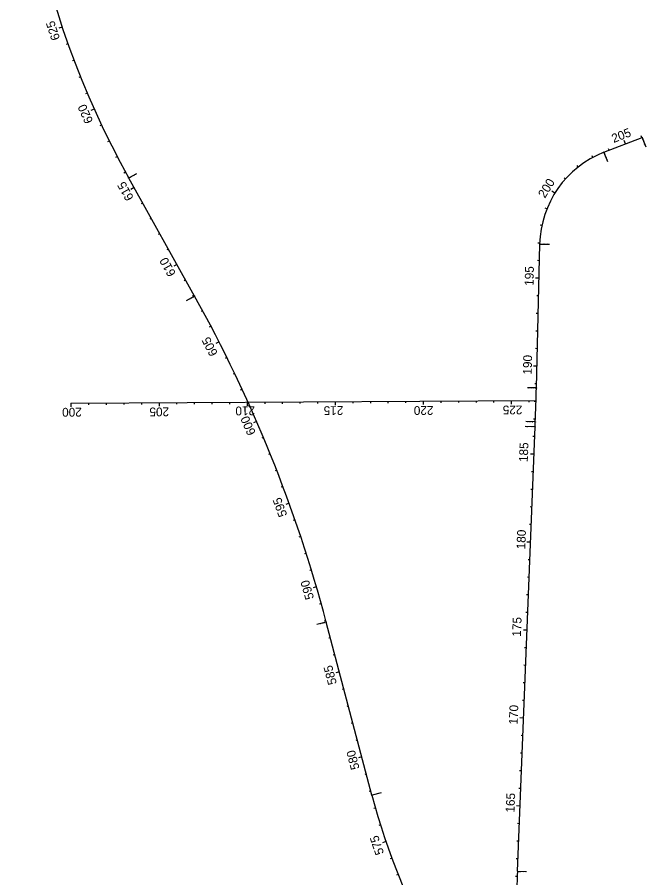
# Model space of a CAD drawing. Extents: x 448091 to 665917, y 1461380 to 1587607.
# Drawn here: x 476716 to 480285, y 1573756 to 1578644 of the extents above; entities that cross this region are included whole.
import ezdxf

# ---------------------------------------------------------------- set-up
doc = ezdxf.new("R2010")
doc.units = 0
for name, color, linetype in [('AttenuatorTM', 7, 'Continuous'), ('BillboardVeg', 7, 'Continuous'), ('BillboardZone', 7, 'Continuous'), ('BLSurvey_dp', 7, 'Continuous'), ('BLSurveyCntrl_ep', 7, 'Continuous'), ('BLSurveyField_ep', 7, 'Continuous'), ('BLSurveySymbl_ep', 7, 'Continuous')]:
    doc.layers.add(name, color=color, linetype=linetype)

msp = doc.modelspace()

# ---------------------------------------------------------------- linework, layer by layer
at = {"layer": 'AttenuatorTM'}
for p, q in [((480264.5, 1577961.2), (480285.3, 1577907.8)), ((480048, 1577875.9), (480068.3, 1577823.8)), ((477350, 1577731), (477394.8, 1577756)), ((479683.5, 1577355.3), (479738.1, 1577354.1)), ((477722.8, 1577059.5), (477676.2, 1577033.5)), ((479663.3, 1576538.6), (479612.9, 1576539.7)), ((479656.1, 1576316.6), (479600.7, 1576318.8)), ((479657.2, 1576345.3), (479604.9, 1576347.4)), ((478470, 1575207.9), (478417.8, 1575194.1)), ((478783.7, 1574238.6), (478731.4, 1574224.8)), ((479557, 1573793.5), (479608.7, 1573791.4))]:
    msp.add_line(p, q, dxfattribs=at)
for centre in [(480264.5, 1577961.2), (480047.7, 1577876.6), (477349.4, 1577730.6), (479682.8, 1577355.3), (477723.4, 1577059.9), (479664, 1576538.5), (479656.8, 1576316.5), (479658, 1576345.3), (478470.7, 1575208.1), (478730.7, 1574224.8), (479556.3, 1573793.5)]:
    msp.add_circle(centre, 0.75, dxfattribs=at)
at = {"layer": 'BillboardVeg'}
for p, q in [((477723.4, 1577059.9), (477349.4, 1577730.6)), ((478730.7, 1574224.8), (478470.7, 1575208.1))]:
    msp.add_line(p, q, dxfattribs=at)
for centre, radius, start, end in [((481716.2, 1580165.9), 5000, 171.5783, 209.1468), ((470736.4, 1573163.5), 8000, 14.80788, 29.14677), ((482597.8, 1575247.1), 4000, 194.8079, 223.3814)]:
    msp.add_arc(centre, radius, start, end, dxfattribs=at)
at = {"layer": 'BLSurvey_dp'}
for p, q in [((476971.9, 1578587.3), (476953, 1578581)), ((477004.5, 1578492.8), (476995, 1578489.4)), ((477038.9, 1578398.9), (477029.5, 1578395.4)), ((477075.1, 1578305.7), (477065.9, 1578302)), ((477113.3, 1578213.3), (477104.1, 1578209.4)), ((477153.2, 1578121.6), (477135, 1578113.4)), ((477195, 1578030.7), (477186, 1578026.5)), ((477238.6, 1577940.8), (477229.7, 1577936.3)), ((477284, 1577851.7), (477275.2, 1577847)), ((477331.2, 1577763.5), (477322.4, 1577758.7)), ((477379.8, 1577676.1), (477362.3, 1577666.3)), ((477428.5, 1577588.7), (477419.8, 1577583.9)), ((477477.2, 1577501.4), (477468.5, 1577496.5)), ((477525.9, 1577414.1), (477517.2, 1577409.2)), ((477574.6, 1577326.7), (477565.9, 1577321.9)), ((477623.3, 1577239.4), (477605.8, 1577229.6)), ((477672, 1577152.1), (477663.3, 1577147.2)), ((477720.7, 1577064.7), (477712, 1577059.8)), ((477768.9, 1576977.1), (477760.1, 1576972.3)), ((477816.1, 1576888.9), (477807.2, 1576884.2)), ((477862.1, 1576800.1), (477844.3, 1576791)), ((477907, 1576710.8), (477898, 1576706.3)), ((477950.7, 1576620.9), (477941.7, 1576616.5)), ((477993.4, 1576530.4), (477984.3, 1576526.2)), ((478034.9, 1576439.4), (478025.8, 1576435.3)), ((478075.3, 1576348), (478057, 1576340)), ((478114.5, 1576256), (478105.3, 1576252.1)), ((478152.6, 1576163.5), (478143.3, 1576159.8)), ((478189.5, 1576070.6), (478180.2, 1576066.9)), ((478225.3, 1575977.2), (478215.9, 1575973.7)), ((478259.9, 1575883.4), (478241.1, 1575876.6)), ((478293.3, 1575789.1), (478283.8, 1575785.8)), ((478325.5, 1575694.4), (478316, 1575691.3)), ((478356.6, 1575599.4), (478347, 1575596.3)), ((478386.4, 1575503.9), (478376.8, 1575501)), ((478415.1, 1575408.1), (478395.9, 1575402.5)), ((478442.5, 1575312), (478432.9, 1575309.3)), ((478468.8, 1575215.5), (478459.1, 1575212.9)), ((478494.3, 1575118.8), (478484.7, 1575116.3)), ((478519.9, 1575022.1), (478510.2, 1575019.6)), ((478545.5, 1574925.5), (478526.1, 1574920.3)), ((478571, 1574828.8), (478561.3, 1574826.2)), ((478596.6, 1574732.1), (478586.9, 1574729.5)), ((478622.1, 1574635.4), (478612.5, 1574632.9)), ((478647.7, 1574538.7), (478638, 1574536.2)), ((478673.2, 1574442.1), (478653.9, 1574437)), ((478698.8, 1574345.4), (478689.1, 1574342.8)), ((478724.4, 1574248.7), (478714.7, 1574246.1)), ((478750.6, 1574152.2), (478741, 1574149.5)), ((478779.2, 1574056.4), (478769.6, 1574053.4)), ((478810.1, 1573961.3), (478791.2, 1573954.9)), ((478843.5, 1573867), (478834.1, 1573863.6)), ((478879.1, 1573773.6), (478869.8, 1573769.9))]:
    msp.add_line(p, q, dxfattribs=at)
at = {"layer": 'BLSurveyCntrl_ep'}
for p, q in [((480047.7, 1577876.6), (480264.5, 1577961.2)), ((479664, 1576538.5), (479682.8, 1577355.3)), ((477021.4, 1576451.6), (479662.2, 1576467.2)), ((479556.3, 1573793.5), (479656.8, 1576316.5)), ((479656.8, 1576316.5), (479658, 1576345.3))]:
    msp.add_line(p, q, dxfattribs=at)
for centre, radius, start, end in [((480256.3, 1577342.2), 573.7, 111.3182, 178.6849), ((468207.8, 1576801.5), 11459.2, 357.71822, 358.68489), ((485281.4, 1573565.4), 5729.6, 177.71823, 179.76808)]:
    msp.add_arc(centre, radius, start, end, dxfattribs=at)
at = {"layer": 'BLSurveyField_ep'}
for p, q in [((480263.2, 1577960.7), (480259.5, 1577970)), ((480170, 1577924.3), (480162.7, 1577943)), ((480076.8, 1577888), (480073.2, 1577897.3)), ((479985.3, 1577847.8), (479980.6, 1577856.7)), ((479901.7, 1577793.2), (479895.6, 1577801)), ((479828.9, 1577724.9), (479821.4, 1577731.5)), ((479769, 1577644.9), (479752, 1577655.5)), ((479723.9, 1577555.8), (479714.6, 1577559.6)), ((479694.9, 1577460.3), (479685.1, 1577462.3)), ((479682.9, 1577361.1), (479672.9, 1577361.4)), ((479680.6, 1577261.1), (479670.6, 1577261.4)), ((479678.3, 1577161.2), (479658.3, 1577161.6)), ((479676, 1577061.2), (479666, 1577061.4)), ((479673.7, 1576961.2), (479663.7, 1576961.4)), ((479671.4, 1576861.2), (479661.4, 1576861.5)), ((479669.1, 1576761.3), (479659.1, 1576761.5)), ((479666.8, 1576661.3), (479646.8, 1576661.8)), ((479664.5, 1576561.3), (479654.5, 1576561.5)), ((477221.4, 1576452.8), (477221.5, 1576442.8)), ((477321.4, 1576453.4), (477321.5, 1576443.4)), ((477421.4, 1576454), (477421.5, 1576444)), ((477521.4, 1576454.6), (477521.5, 1576434.6)), ((477621.4, 1576455.2), (477621.5, 1576445.2)), ((477721.4, 1576455.8), (477721.5, 1576445.8)), ((477821.4, 1576456.3), (477821.5, 1576446.3)), ((477921.4, 1576456.9), (477921.5, 1576446.9)), ((478021.4, 1576457.5), (478021.5, 1576437.5)), ((478121.4, 1576458.1), (478121.5, 1576448.1)), ((478221.4, 1576458.7), (478221.5, 1576448.7)), ((478321.4, 1576459.3), (478321.5, 1576449.3)), ((478421.4, 1576459.9), (478421.5, 1576449.9)), ((478521.4, 1576460.5), (478521.5, 1576440.5)), ((478621.4, 1576461), (478621.5, 1576451)), ((478721.4, 1576461.6), (478721.5, 1576451.6)), ((478821.4, 1576462.2), (478821.5, 1576452.2)), ((478921.4, 1576462.8), (478921.5, 1576452.8)), ((479021.4, 1576463.4), (479021.5, 1576443.4)), ((479121.4, 1576464), (479121.5, 1576454)), ((479221.4, 1576464.6), (479221.5, 1576454.6)), ((479321.4, 1576465.2), (479321.5, 1576455.2)), ((479421.4, 1576465.8), (479421.4, 1576455.8)), ((479521.4, 1576466.3), (479521.5, 1576446.3)), ((479621.4, 1576466.9), (479621.4, 1576456.9)), ((479662, 1576461.4), (479652, 1576461.6)), ((477021.4, 1576451.6), (477021.5, 1576431.6)), ((477121.4, 1576452.2), (477121.5, 1576442.2)), ((479658.6, 1576361.4), (479648.6, 1576361.8)), ((479654.6, 1576261.5), (479644.6, 1576261.9)), ((479650.6, 1576161.6), (479630.6, 1576162.4)), ((479646.6, 1576061.6), (479636.7, 1576062)), ((479642.7, 1575961.7), (479632.7, 1575962.1)), ((479638.7, 1575861.8), (479628.7, 1575862.2)), ((479634.7, 1575761.9), (479624.7, 1575762.3)), ((479630.7, 1575662), (479610.7, 1575662.8)), ((479626.7, 1575562), (479616.7, 1575562.4)), ((479622.8, 1575462.1), (479612.8, 1575462.5)), ((479618.8, 1575362.2), (479608.8, 1575362.6)), ((479614.8, 1575262.3), (479604.8, 1575262.7)), ((479610.8, 1575162.4), (479590.8, 1575163.2)), ((479606.8, 1575062.4), (479596.8, 1575062.8)), ((479602.9, 1574962.5), (479592.9, 1574962.9)), ((479598.9, 1574862.6), (479588.9, 1574863)), ((479594.9, 1574762.7), (479584.9, 1574763.1)), ((479590.9, 1574662.8), (479570.9, 1574663.6)), ((479586.9, 1574562.8), (479576.9, 1574563.2)), ((479582.9, 1574462.9), (479573, 1574463.3)), ((479579, 1574363), (479569, 1574363.4)), ((479575, 1574263.1), (479565, 1574263.5)), ((479571, 1574163.2), (479551, 1574164)), ((479567, 1574063.2), (479557, 1574063.6)), ((479563, 1573963.3), (479553, 1573963.7)), ((479559.1, 1573863.4), (479549.1, 1573863.8)), ((479555.2, 1573763.5), (479545.2, 1573763.8))]:
    msp.add_line(p, q, dxfattribs=at)

# ---------------------------------------------------------------- texts
at = {"layer": 'AttenuatorTM'}
for s, rotation, p in [('POT STA. 206+01.40', 111.3182, (480283.3, 1577909.2)), ('PT STA. 203+68.77', 291.3182, (480049.8, 1577875.3)), ('PC STA. 615+62.48', 209.1468, (477394, 1577754.2)), ('PC STA. 196+94.24', 358.6849, (479684.8, 1577356.7)), ('PT STA. 607+94.44', 209.1468, (477722.4, 1577057.7)), ('PT STA. 188+77.21', 178.6849, (479662, 1576537.2)), ('POT STA. 186+55.08', 177.7182, (479654.8, 1576315.2)), ('PC STA. 186+83.88', 177.7182, (479655, 1576344.3)), ('PC STA. 587+92.35', 194.8079, (478469.2, 1575206.2)), ('PT STA. 577+75.24', 194.8079, (478780.8, 1574242.4)), ('PT STA. 161+30.04', 357.7182, (479559.8, 1573787.6))]:
    msp.add_text(s, height=3.5, rotation=rotation, dxfattribs=at).set_placement(p)
at = {"layer": 'BillboardZone'}
for s, rotation, p in [('625', 108.4036, (476960.1, 1578522.3)), ('620', 114.1331, (477148.8, 1578053.3)), ('615', 119.1468, (477379.7, 1577618.3)), ('610', 119.1468, (477619.2, 1577188.2)), ('605', 117.038, (477856.9, 1576734.1)), ('600', 113.457, (478072.3, 1576282.3)), ('595', 109.876, (478250.3, 1575816.1)), ('590', 106.2951, (478402.4, 1575344.3)), ('585', 104.8079, (478531.5, 1574859.2)), ('580', 104.8079, (478660.9, 1574377.2)), ('575', 108.7504, (478799.9, 1573895.3))]:
    msp.add_text(s, height=50, rotation=rotation, dxfattribs=at).set_placement(p)
at = {"layer": 'BLSurveySymbl_ep'}
for s, rotation, p in [('205', 21.3182, (480103, 1577929.3)), ('200', 58.1478, (479712.6, 1577612.8)), ('195', 88.6849, (479647.5, 1577117.6)), ('190', 88.6849, (479637.5, 1576613.5)), ('200', 180.3372, (477082.7, 1576425.7)), ('205', 180.3372, (477578.4, 1576427.4)), ('210', 180.3372, (478066.5, 1576433.2)), ('215', 180.3372, (478567.7, 1576434.9)), ('220', 180.3372, (479079.5, 1576435.4)), ('225', 180.3372, (479584.6, 1576438.4)), ('185', 87.7182, (479614.8, 1576116.6)), ('180', 87.7182, (479600.8, 1575620.8)), ('175', 87.7182, (479576, 1575124.4)), ('170', 87.7182, (479557.5, 1574625.3)), ('165', 87.7182, (479539.3, 1574125.3))]:
    msp.add_text(s, height=50, rotation=rotation, dxfattribs=at).set_placement(p)

doc.saveas('drawing.dxf')
